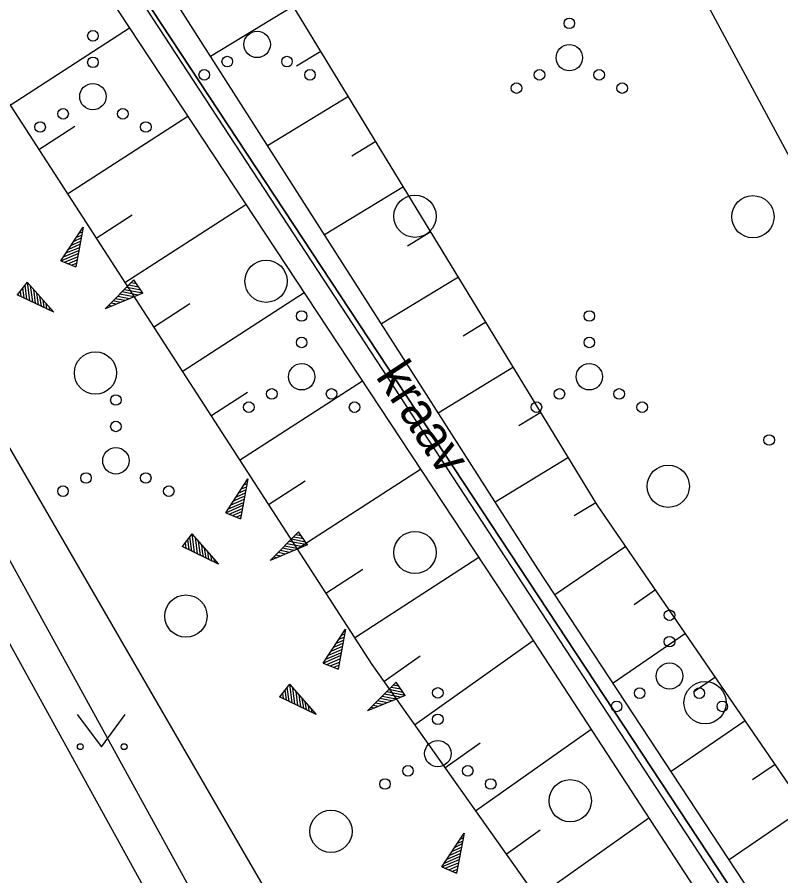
# Model space of a CAD drawing. Extents: x 554947 to 555436, y 6564938 to 6565792.
# Drawn here: x 555242.09 to 555256.53, y 6565114.23 to 6565130.48 of the extents above; entities that cross this region are included whole.
import ezdxf

# ---------------------------------------------------------------- set-up
doc = ezdxf.new("R2010")
doc.units = 0
for name, color, linetype in [('HALJASTUS', 7, 'Continuous'), ('MPKAABEL', 7, 'Continuous'), ('PIIR', 7, 'Continuous'), ('PR_SIDE', 7, 'Continuous'), ('RELJEEF', 7, 'Continuous'), ('VEEKOGU', 7, 'Continuous')]:
    doc.layers.add(name, color=color, linetype=linetype)

msp = doc.modelspace()

# ---------------------------------------------------------------- linework, layer by layer
at = {"layer": 'HALJASTUS'}
for p, q in [((555243.221, 6565117.279), (555243.684, 6565116.673)), ((555243.684, 6565116.673), (555244.13, 6565117.279))]:
    msp.add_line(p, q, dxfattribs=at)
for points in [[(555235.12, 6565151.155), (555232.135, 6565148.949), (555229.151, 6565146.49), (555228.521, 6565144.196), (555233.66, 6565136.637), (555246.422, 6565114.586), (555255.514, 6565098.946)], [(555277.06, 6565106.584), (555277.255, 6565111.788), (555268.557, 6565110.949), (555265.778, 6565110.936), (555262.384, 6565108.727), (555261.075, 6565113.375), (555263.858, 6565115.236), (555262.795, 6565117.659), (555261.001, 6565121.133), (555260.129, 6565122.751), (555257.76, 6565125.864), (555253.762, 6565133.295), (555248.914, 6565136.251)]]:
    msp.add_lwpolyline(points, dxfattribs=at)
for centre, radius in [((555252.534, 6565130.359), 0.1), ((555243.522, 6565130.122), 0.1), ((555246.628, 6565129.96), 0.25), ((555252.534, 6565129.709), 0.25), ((555243.522, 6565129.622), 0.1), ((555246.063, 6565129.635), 0.1), ((555247.193, 6565129.635), 0.1), ((555245.628, 6565129.385), 0.1), ((555247.628, 6565129.385), 0.1), ((555251.969, 6565129.384), 0.1), ((555253.099, 6565129.384), 0.1), ((555243.522, 6565128.972), 0.25), ((555251.534, 6565129.134), 0.1), ((555253.534, 6565129.134), 0.1), ((555242.957, 6565128.647), 0.1), ((555244.087, 6565128.647), 0.1), ((555242.522, 6565128.397), 0.1), ((555244.522, 6565128.397), 0.1), ((555249.614, 6565126.709), 0.4), ((555256.007, 6565126.7), 0.4), ((555246.797, 6565125.479), 0.4), ((555247.471, 6565124.822), 0.1), ((555252.912, 6565124.822), 0.1), ((555247.471, 6565124.322), 0.1), ((555252.912, 6565124.322), 0.1), ((555243.57, 6565123.744), 0.4), ((555247.471, 6565123.672), 0.25), ((555252.912, 6565123.672), 0.25), ((555243.956, 6565123.232), 0.1), ((555246.906, 6565123.347), 0.1), ((555248.036, 6565123.347), 0.1), ((555252.347, 6565123.347), 0.1), ((555253.477, 6565123.347), 0.1), ((555246.471, 6565123.097), 0.1), ((555248.471, 6565123.097), 0.1), ((555251.912, 6565123.097), 0.1), ((555253.912, 6565123.097), 0.1), ((555243.956, 6565122.732), 0.1), ((555256.315, 6565122.475), 0.1), ((555243.956, 6565122.082), 0.25), ((555254.405, 6565121.6), 0.4), ((555243.391, 6565121.757), 0.1), ((555244.521, 6565121.757), 0.1), ((555242.956, 6565121.507), 0.1), ((555244.956, 6565121.507), 0.1), ((555249.614, 6565120.347), 0.4), ((555245.28, 6565119.143), 0.4), ((555254.429, 6565119.16), 0.1), ((555254.429, 6565118.66), 0.1), ((555254.429, 6565118.01), 0.25), ((555255.103, 6565117.505), 0.4), ((555250.047, 6565117.691), 0.1), ((555253.864, 6565117.685), 0.1), ((555254.994, 6565117.685), 0.1), ((555253.429, 6565117.435), 0.1), ((555255.429, 6565117.435), 0.1), ((555250.047, 6565117.191), 0.1), ((555243.283, 6565116.673), 0.055), ((555244.112, 6565116.673), 0.055), ((555250.047, 6565116.541), 0.25), ((555249.482, 6565116.216), 0.1), ((555250.612, 6565116.216), 0.1), ((555249.047, 6565115.966), 0.1), ((555251.047, 6565115.966), 0.1), ((555252.551, 6565115.65), 0.4), ((555248.025, 6565115.071), 0.4)]:
    msp.add_circle(centre, radius, dxfattribs=at)
at = {"layer": 'MPKAABEL'}
msp.add_lwpolyline([(555252.588, 6565101.946), (555250.157, 6565105.485), (555246.43, 6565112.048), (555243.328, 6565117.686), (555240.248, 6565123.284), (555235.885, 6565131.607), (555233.393, 6565136.173), (555233.034, 6565137.981), (555233.62, 6565138.358), (555237.1, 6565137.907), (555242.704, 6565136.954), (555245.573, 6565136.455), (555256.506, 6565134.49), (555262.887, 6565133.288), (555269.268, 6565132.087), (555280.849, 6565129.896), (555289.168, 6565128.301), (555288.207, 6565123.189), (555286.959, 6565118.589), (555293.983, 6565117.646), (555297.167, 6565117.091)], dxfattribs=at)
at = {"layer": 'PIIR'}
for points in [[(555293.54, 6565286.23), (555256.63, 6565245.54), (555254.61, 6565228.5), (555255.75, 6565226.79), (555261.42, 6565218.27), (555289.11, 6565186.6), (555315.28, 6565149.09), (555315.73, 6565134.86), (555310.07, 6565124.47), (555303.59, 6565115.89), (555291.54, 6565100.48), (555288.85, 6565092.31), (555275.41, 6565088.83), (555273.15, 6565087.34), (555239.11, 6565139), (555231.12, 6565150.64), (555225.89, 6565157.13), (555173.21, 6565166.35), (555173.84, 6565168.77), (555191.64, 6565237.48), (555195.28, 6565271.63)], [(555272.013, 6565013.369), (555140.74, 6565041.04), (555172.58, 6565163.93), (555173.21, 6565166.35), (555225.89, 6565157.13), (555231.12, 6565150.64), (555239.11, 6565139), (555273.15, 6565087.34), (555275.41, 6565088.83), (555288.85, 6565092.31), (555289.83, 6565088.53), (555290.166, 6565088.221)]]:
    msp.add_lwpolyline(points, dxfattribs=at)
at = {"layer": 'PR_SIDE'}
msp.add_lwpolyline([(555231.314, 6565137.915), (555250.156, 6565103.719), (555250, 6565102), (555221.076, 6565087.78)], dxfattribs=at)
at = {"layer": 'RELJEEF'}
for p, q in [((555247.314, 6565130.683), (555245.748, 6565129.729)), ((555241.954, 6565128.812), (555244.214, 6565130.273)), ((555247.834, 6565129.829), (555247.37, 6565129.546)), ((555248.355, 6565128.975), (555246.825, 6565128.043)), ((555243.04, 6565127.133), (555245.315, 6565128.604)), ((555242.497, 6565127.973), (555243.177, 6565128.412)), ((555248.875, 6565128.121), (555248.421, 6565127.845)), ((555249.395, 6565127.267), (555247.902, 6565126.357)), ((555244.125, 6565125.453), (555246.416, 6565126.934)), ((555243.583, 6565126.293), (555244.267, 6565126.736)), ((555242.917, 6565125.864), (555243.337, 6565126.504)), ((555243.337, 6565126.504), (555243.197, 6565125.749)), ((555243.262, 6565126.389), (555243.322, 6565126.414)), ((555243.312, 6565126.464), (555243.332, 6565126.474)), ((555249.916, 6565126.413), (555249.473, 6565126.143)), ((555243.167, 6565126.239), (555243.297, 6565126.299)), ((555243.212, 6565126.314), (555243.312, 6565126.354)), ((555243.017, 6565126.014), (555243.267, 6565126.119)), ((555243.067, 6565126.089), (555243.192, 6565126.144)), ((555243.117, 6565126.164), (555243.287, 6565126.239)), ((555243.192, 6565126.144), (555243.277, 6565126.179)), ((555242.917, 6565125.864), (555243.242, 6565126.004)), ((555242.967, 6565125.939), (555243.252, 6565126.059)), ((555242.982, 6565125.839), (555243.232, 6565125.944)), ((555242.917, 6565125.864), (555243.197, 6565125.749)), ((555242.917, 6565125.864), (555242.917, 6565125.864)), ((555243.047, 6565125.809), (555243.222, 6565125.884)), ((555243.117, 6565125.784), (555243.212, 6565125.824)), ((555243.182, 6565125.759), (555243.197, 6565125.764)), ((555242.276, 6565125.463), (555242.091, 6565125.223)), ((555242.276, 6565125.463), (555242.781, 6565124.893)), ((555242.276, 6565125.463), (555242.321, 6565125.113)), ((555242.276, 6565125.463), (555242.276, 6565125.463)), ((555243.755, 6565124.958), (555244.295, 6565125.503)), ((555244.345, 6565125.428), (555244.245, 6565125.448)), ((555244.305, 6565125.488), (555244.285, 6565125.488)), ((555244.465, 6565125.253), (555244.295, 6565125.503)), ((555250.436, 6565125.559), (555248.978, 6565124.671)), ((555242.146, 6565125.293), (555242.161, 6565125.193)), ((555242.191, 6565125.353), (555242.216, 6565125.168)), ((555242.231, 6565125.408), (555242.266, 6565125.138)), ((555242.336, 6565125.398), (555242.376, 6565125.088)), ((555242.396, 6565125.328), (555242.431, 6565125.063)), ((555244.38, 6565125.218), (555244.075, 6565125.278)), ((555244.465, 6565125.253), (555244.115, 6565125.318)), ((555244.425, 6565125.308), (555244.16, 6565125.363)), ((555244.385, 6565125.368), (555244.2, 6565125.403)), ((555242.781, 6565124.893), (555242.091, 6565125.223)), ((555242.101, 6565125.238), (555242.106, 6565125.218)), ((555242.456, 6565125.263), (555242.471, 6565125.123)), ((555242.471, 6565125.123), (555242.486, 6565125.033)), ((555242.511, 6565125.193), (555242.541, 6565125.008)), ((555242.571, 6565125.128), (555242.591, 6565124.983)), ((555244.465, 6565125.253), (555243.755, 6565124.958)), ((555244.045, 6565125.078), (555243.905, 6565125.108)), ((555244.13, 6565125.113), (555243.945, 6565125.148)), ((555244.08, 6565125.173), (555243.99, 6565125.193)), ((555244.295, 6565125.183), (555244.03, 6565125.233)), ((555244.215, 6565125.148), (555244.08, 6565125.173)), ((555244.465, 6565125.253), (555244.465, 6565125.253)), ((555245.211, 6565123.774), (555247.517, 6565125.264)), ((555242.631, 6565125.058), (555242.646, 6565124.958)), ((555242.691, 6565124.993), (555242.701, 6565124.928)), ((555243.795, 6565124.973), (555243.78, 6565124.978)), ((555243.88, 6565125.008), (555243.82, 6565125.023)), ((555243.965, 6565125.043), (555243.86, 6565125.063)), ((555244.668, 6565124.613), (555245.358, 6565125.059)), ((555242.751, 6565124.923), (555242.756, 6565124.903)), ((555250.956, 6565124.705), (555250.524, 6565124.442)), ((555251.477, 6565123.851), (555250.055, 6565122.985)), ((555246.297, 6565122.094), (555248.619, 6565123.595)), ((555245.754, 6565122.934), (555246.448, 6565123.383)), ((555251.997, 6565122.997), (555251.576, 6565122.741)), ((555252.517, 6565122.143), (555251.132, 6565121.299)), ((555247.383, 6565120.414), (555249.72, 6565121.925)), ((555246.035, 6565121.1), (555246.455, 6565121.74)), ((555246.455, 6565121.74), (555246.315, 6565120.985)), ((555246.43, 6565121.7), (555246.45, 6565121.71)), ((555246.84, 6565121.254), (555247.539, 6565121.706)), ((555246.285, 6565121.475), (555246.415, 6565121.535)), ((555246.33, 6565121.55), (555246.43, 6565121.59)), ((555246.38, 6565121.625), (555246.44, 6565121.65)), ((555246.185, 6565121.325), (555246.31, 6565121.38)), ((555246.235, 6565121.4), (555246.405, 6565121.475)), ((555246.31, 6565121.38), (555246.395, 6565121.415)), ((555246.035, 6565121.1), (555246.36, 6565121.24)), ((555246.085, 6565121.175), (555246.37, 6565121.295)), ((555246.135, 6565121.25), (555246.385, 6565121.355)), ((555253.038, 6565121.289), (555252.627, 6565121.039)), ((555246.035, 6565121.1), (555246.315, 6565120.985)), ((555246.035, 6565121.1), (555246.035, 6565121.1)), ((555246.1, 6565121.075), (555246.35, 6565121.18)), ((555246.165, 6565121.045), (555246.34, 6565121.12)), ((555246.235, 6565121.02), (555246.33, 6565121.06)), ((555246.3, 6565120.995), (555246.315, 6565121)), ((555246.873, 6565120.194), (555247.413, 6565120.739)), ((555247.423, 6565120.724), (555247.403, 6565120.724)), ((555247.583, 6565120.489), (555247.413, 6565120.739)), ((555245.394, 6565120.699), (555245.209, 6565120.459)), ((555245.309, 6565120.589), (555245.334, 6565120.404)), ((555245.349, 6565120.644), (555245.384, 6565120.374)), ((555245.394, 6565120.699), (555245.899, 6565120.129)), ((555245.394, 6565120.699), (555245.439, 6565120.349)), ((555245.394, 6565120.699), (555245.394, 6565120.699)), ((555245.454, 6565120.634), (555245.494, 6565120.324)), ((555245.514, 6565120.564), (555245.549, 6565120.299)), ((555247.543, 6565120.544), (555247.278, 6565120.599)), ((555247.503, 6565120.604), (555247.318, 6565120.639)), ((555247.463, 6565120.664), (555247.363, 6565120.684)), ((555245.899, 6565120.129), (555245.209, 6565120.459)), ((555245.219, 6565120.474), (555245.224, 6565120.454)), ((555245.264, 6565120.529), (555245.279, 6565120.429)), ((555245.574, 6565120.499), (555245.589, 6565120.359)), ((555245.629, 6565120.429), (555245.659, 6565120.244)), ((555247.583, 6565120.489), (555246.873, 6565120.194)), ((555247.198, 6565120.409), (555247.108, 6565120.429)), ((555247.413, 6565120.419), (555247.148, 6565120.469)), ((555247.498, 6565120.454), (555247.193, 6565120.514)), ((555247.333, 6565120.384), (555247.198, 6565120.409)), ((555247.583, 6565120.489), (555247.233, 6565120.554)), ((555247.583, 6565120.489), (555247.583, 6565120.489)), ((555253.601, 6565120.463), (555252.262, 6565119.545)), ((555245.589, 6565120.359), (555245.604, 6565120.269)), ((555245.689, 6565120.364), (555245.709, 6565120.219)), ((555245.749, 6565120.294), (555245.764, 6565120.194)), ((555246.998, 6565120.244), (555246.938, 6565120.259)), ((555247.083, 6565120.279), (555246.978, 6565120.299)), ((555247.163, 6565120.314), (555247.023, 6565120.344)), ((555247.248, 6565120.349), (555247.063, 6565120.384)), ((555248.469, 6565118.735), (555250.821, 6565120.256)), ((555245.809, 6565120.229), (555245.819, 6565120.164)), ((555245.869, 6565120.159), (555245.874, 6565120.139)), ((555246.913, 6565120.209), (555246.898, 6565120.214)), ((555247.926, 6565119.575), (555248.629, 6565120.029)), ((555254.166, 6565119.638), (555253.76, 6565119.359)), ((555247.879, 6565118.255), (555248.299, 6565118.895)), ((555248.299, 6565118.895), (555248.159, 6565118.14)), ((555248.224, 6565118.78), (555248.284, 6565118.805)), ((555248.274, 6565118.855), (555248.294, 6565118.865)), ((555254.731, 6565118.813), (555253.361, 6565117.874)), ((555248.079, 6565118.555), (555248.249, 6565118.63)), ((555248.129, 6565118.63), (555248.259, 6565118.69)), ((555248.174, 6565118.705), (555248.274, 6565118.745)), ((555249.603, 6565117.088), (555251.853, 6565118.681)), ((555247.929, 6565118.33), (555248.214, 6565118.45)), ((555247.979, 6565118.405), (555248.229, 6565118.51)), ((555248.029, 6565118.48), (555248.154, 6565118.535)), ((555248.154, 6565118.535), (555248.239, 6565118.57)), ((555247.879, 6565118.255), (555248.204, 6565118.395)), ((555247.944, 6565118.23), (555248.194, 6565118.335)), ((555249.025, 6565117.904), (555249.71, 6565118.389)), ((555247.879, 6565118.255), (555248.159, 6565118.14)), ((555247.879, 6565118.255), (555247.879, 6565118.255)), ((555248.009, 6565118.2), (555248.184, 6565118.275)), ((555248.079, 6565118.175), (555248.174, 6565118.215)), ((555248.144, 6565118.15), (555248.159, 6565118.155)), ((555255.297, 6565117.988), (555254.881, 6565117.703)), ((555247.238, 6565117.854), (555247.053, 6565117.614)), ((555247.193, 6565117.799), (555247.228, 6565117.529)), ((555247.238, 6565117.854), (555247.743, 6565117.284)), ((555247.238, 6565117.854), (555247.283, 6565117.504)), ((555247.238, 6565117.854), (555247.238, 6565117.854)), ((555248.717, 6565117.349), (555249.257, 6565117.894)), ((555249.307, 6565117.819), (555249.207, 6565117.839)), ((555249.267, 6565117.879), (555249.247, 6565117.879)), ((555249.427, 6565117.644), (555249.257, 6565117.894)), ((555247.108, 6565117.684), (555247.123, 6565117.584)), ((555247.153, 6565117.744), (555247.178, 6565117.559)), ((555247.298, 6565117.789), (555247.338, 6565117.479)), ((555247.358, 6565117.719), (555247.393, 6565117.454)), ((555247.418, 6565117.654), (555247.433, 6565117.514)), ((555249.427, 6565117.644), (555248.717, 6565117.349)), ((555249.342, 6565117.609), (555249.037, 6565117.669)), ((555249.427, 6565117.644), (555249.077, 6565117.709)), ((555249.387, 6565117.699), (555249.122, 6565117.754)), ((555249.347, 6565117.759), (555249.162, 6565117.794)), ((555249.427, 6565117.644), (555249.427, 6565117.644)), ((555247.743, 6565117.284), (555247.053, 6565117.614)), ((555247.063, 6565117.629), (555247.068, 6565117.609)), ((555247.433, 6565117.514), (555247.448, 6565117.424)), ((555247.473, 6565117.584), (555247.503, 6565117.399)), ((555247.533, 6565117.519), (555247.553, 6565117.374)), ((555249.007, 6565117.469), (555248.867, 6565117.499)), ((555249.092, 6565117.504), (555248.907, 6565117.539)), ((555249.042, 6565117.564), (555248.952, 6565117.584)), ((555249.257, 6565117.574), (555248.992, 6565117.624)), ((555249.177, 6565117.539), (555249.042, 6565117.564)), ((555247.593, 6565117.449), (555247.608, 6565117.349)), ((555247.653, 6565117.384), (555247.663, 6565117.319)), ((555247.713, 6565117.314), (555247.718, 6565117.294)), ((555248.757, 6565117.364), (555248.742, 6565117.369)), ((555248.842, 6565117.399), (555248.782, 6565117.414)), ((555248.927, 6565117.434), (555248.822, 6565117.454)), ((555255.862, 6565117.163), (555254.46, 6565116.202)), ((555250.759, 6565115.456), (555252.946, 6565117.005)), ((555250.181, 6565116.272), (555250.847, 6565116.743)), ((555256.427, 6565116.338), (555256.002, 6565116.047)), ((555256.993, 6565115.514), (555255.559, 6565114.531)), ((555251.915, 6565113.824), (555254.038, 6565115.328)), ((555250.122, 6565114.397), (555250.542, 6565115.037)), ((555250.542, 6565115.037), (555250.402, 6565114.282)), ((555251.337, 6565114.64), (555251.984, 6565115.098)), ((555250.417, 6565114.847), (555250.517, 6565114.887)), ((555250.467, 6565114.922), (555250.527, 6565114.947)), ((555250.517, 6565114.997), (555250.537, 6565115.007)), ((555250.322, 6565114.697), (555250.492, 6565114.772)), ((555250.372, 6565114.772), (555250.502, 6565114.832)), ((555250.397, 6565114.677), (555250.482, 6565114.712)), ((555250.172, 6565114.472), (555250.457, 6565114.592)), ((555250.222, 6565114.547), (555250.472, 6565114.652)), ((555250.272, 6565114.622), (555250.397, 6565114.677)), ((555250.122, 6565114.397), (555250.447, 6565114.537)), ((555250.122, 6565114.397), (555250.402, 6565114.282)), ((555250.122, 6565114.397), (555250.122, 6565114.397)), ((555250.187, 6565114.372), (555250.437, 6565114.477)), ((555250.252, 6565114.342), (555250.427, 6565114.417)), ((555250.322, 6565114.317), (555250.417, 6565114.357)), ((555250.387, 6565114.292), (555250.402, 6565114.297))]:
    msp.add_line(p, q, dxfattribs=at)
msp.add_lwpolyline([(555267.243, 6565100.718), (555264.574, 6565104.451), (555253.061, 6565121.25), (555242.65, 6565138.338), (555234.145, 6565148.829), (555233.386, 6565148.636), (555231.367, 6565148.23), (555230.85, 6565146.543), (555236.09, 6565137.882), (555248.799, 6565118.225), (555259.289, 6565103.411), (555261.934, 6565099.868)], dxfattribs=at)
at = {"layer": 'VEEKOGU'}
for points in [[(555265.45, 6565099.986), (555262.604, 6565103.817), (555251.937, 6565120.038), (555239.993, 6565138.74), (555233.721, 6565147.576), (555233.071, 6565146.869), (555239.071, 6565138.07), (555251.323, 6565119.495), (555261.764, 6565103.47), (555264.187, 6565099.861)], [(555239.299, 6565138.626), (555251.662, 6565119.733), (555262.176, 6565103.668)]]:
    msp.add_lwpolyline(points, dxfattribs=at)

# ---------------------------------------------------------------- texts
msp.add_text('kraav', height=0.7, rotation=303.3628, dxfattribs=at).set_placement((555248.858, 6565123.676))

doc.saveas('drawing.dxf')
